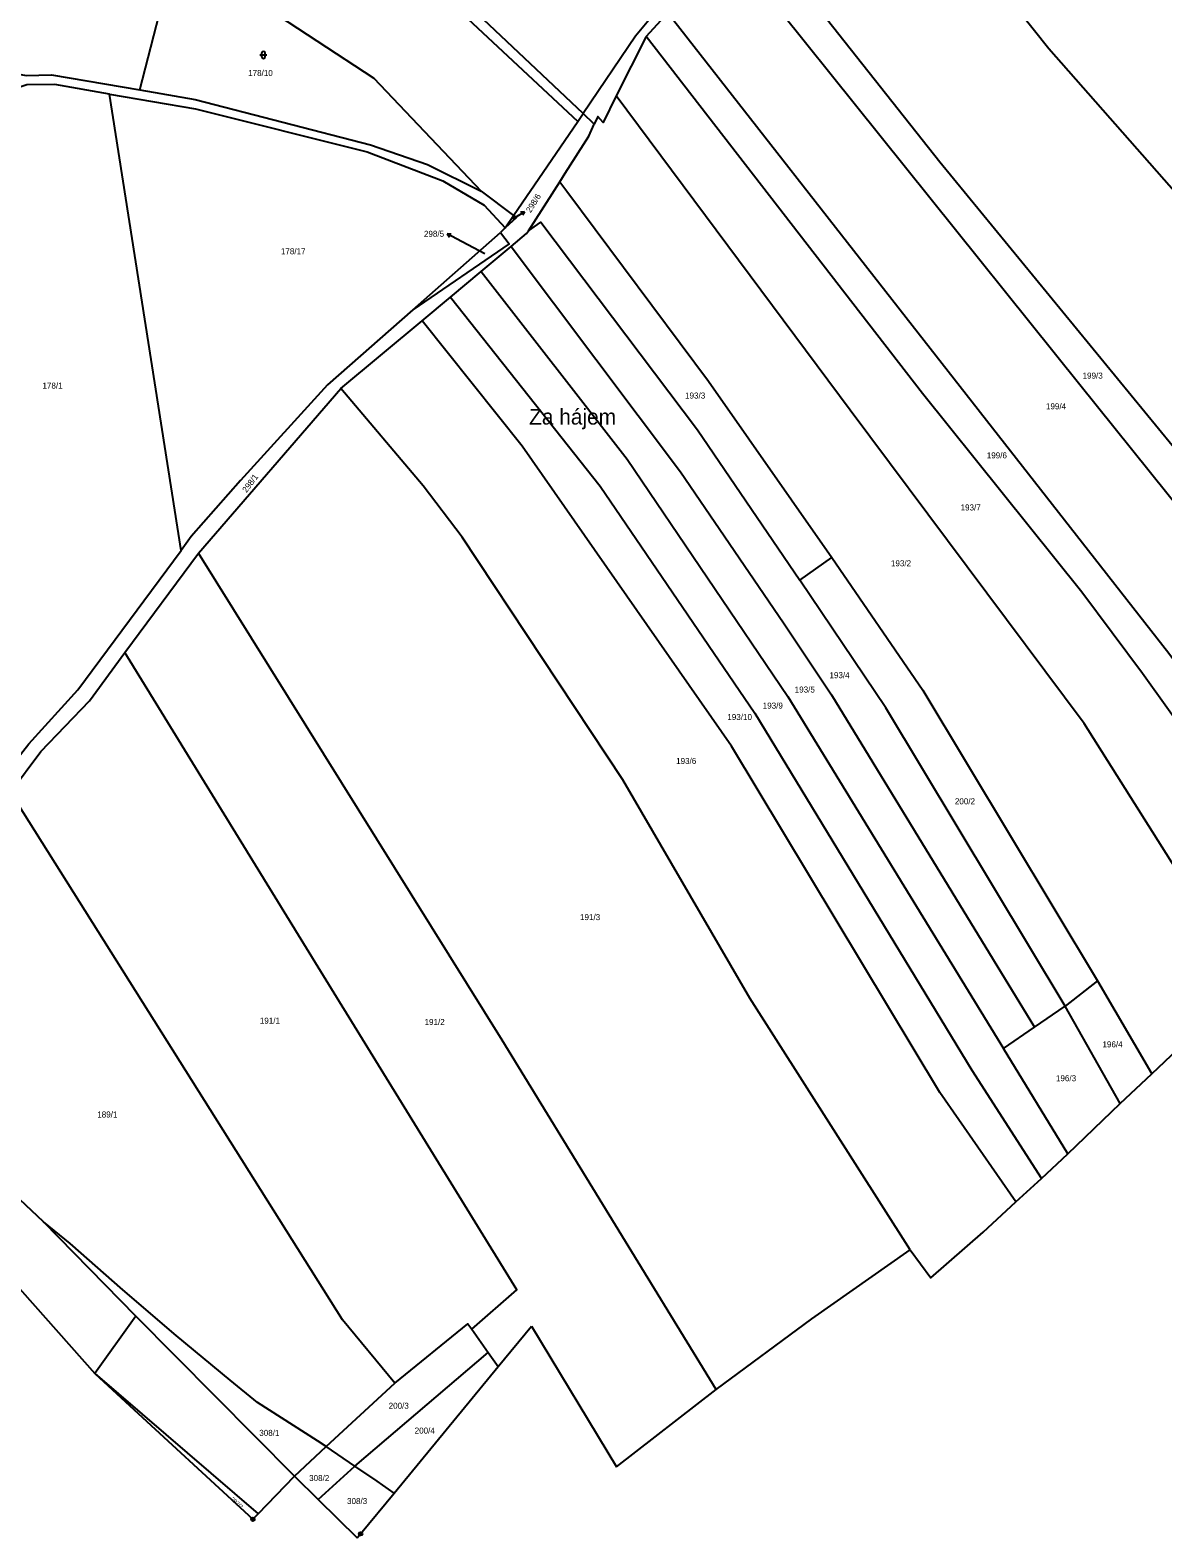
# Model space of a CAD drawing. Extents: x -779723 to -777378, y -1011169 to -1009297.
# Drawn here: x -779294.8 to -778975.2, y -1011169.3 to -1010743.9 of the extents above; entities that cross this region are included whole.
import ezdxf

# ---------------------------------------------------------------- set-up
doc = ezdxf.new("R2010")
doc.units = 0
for name, color, linetype in [('Hranice parcel', 7, 'Continuous'), ('Parcelní čísla', 7, 'Continuous'), ('Pop  PČ popisy', 7, 'Continuous'), ('Vnitřní kresba', 7, 'Continuous'), ('Značky bodu BP', 7, 'Continuous'), ('Značky kultur', 7, 'Continuous')]:
    doc.layers.add(name, color=color, linetype=linetype)

msp = doc.modelspace()

# ---------------------------------------------------------------- linework, layer by layer
at = {"layer": 'Hranice parcel'}
for p, q in [((-779114.85, -1010739.08), (-779121, -1010745.73)), ((-779121, -1010745.73), (-779129.44, -1010762.47)), ((-779252.21, -1010890.71), (-779272.43, -1010762.01)), ((-779140.28, -1010769.67), (-779138.78, -1010767.46)), ((-779135.61, -1010770.46), (-779138.78, -1010767.46)), ((-779154.19, -1010800.5), (-779145.37, -1010786.69)), ((-779167.5, -1010789.36), (-779158.36, -1010796.23)), ((-779160.74, -1010799.73), (-779162.08, -1010801.02)), ((-779160.74, -1010799.73), (-779158.36, -1010796.23)), ((-779186.85, -1010822.84), (-779162.08, -1010801.02)), ((-779167.52, -1010812.01), (-779159.1, -1010804.99)), ((-779176.17, -1010819.22), (-779167.52, -1010812.01)), ((-779184.17, -1010825.9), (-779176.17, -1010819.22)), ((-779207.15, -1010845.06), (-779184.17, -1010825.9)), ((-779247.3, -1010891.46), (-779207.15, -1010845.06)), ((-779268.1, -1010919.48), (-779247.3, -1010891.46)), ((-779077.58, -1010899.08), (-779068.64, -1010892.72)), ((-778993.64, -1011012.17), (-779002.79, -1011019.26)), ((-778993.64, -1011012.17), (-778978.29, -1011038.33)), ((-778978.29, -1011038.33), (-778951.63, -1011012.88)), ((-779011.43, -1011025.21), (-779002.79, -1011019.26)), ((-778987.21, -1011046.72), (-779002.79, -1011019.26)), ((-779020.18, -1011031.25), (-779011.43, -1011025.21)), ((-779002, -1011060.92), (-779020.18, -1011031.25)), ((-778987.21, -1011046.72), (-778978.29, -1011038.33)), ((-779291.02, -1011080.11), (-779333.53, -1011040.14)), ((-779002, -1011060.92), (-778987.21, -1011046.72)), ((-779009.48, -1011067.84), (-779002, -1011060.92)), ((-779016.68, -1011074.49), (-779009.48, -1011067.84)), ((-779320.15, -1011073.73), (-779276.53, -1011122.92)), ((-779170.13, -1011110.43), (-779165.54, -1011116.95)), ((-779162.74, -1011120.93), (-779153.37, -1011109.53)), ((-779153.37, -1011109.53), (-779129.33, -1011149.2)), ((-779203.15, -1011149.01), (-779165.54, -1011116.95)), ((-779165.54, -1011116.95), (-779162.74, -1011120.93)), ((-779276.53, -1011122.92), (-779230.46, -1011162.5)), ((-779276.53, -1011122.92), (-779269.1, -1011129.77)), ((-779192.08, -1011156.62), (-779162.74, -1011120.93)), ((-779211.28, -1011143.53), (-779191.88, -1011125.67)), ((-779129.33, -1011149.2), (-779101.21, -1011127.39)), ((-779269.1, -1011129.77), (-779231.93, -1011164.02)), ((-779220.18, -1011151.87), (-779211.28, -1011143.53)), ((-779203.15, -1011149.01), (-779211.28, -1011143.53)), ((-779213.5, -1011158.46), (-779203.15, -1011149.01)), ((-779230.46, -1011162.5), (-779220.18, -1011151.87)), ((-779220.18, -1011151.87), (-779213.5, -1011158.46)), ((-779201.55, -1011168.14), (-779192.08, -1011156.62)), ((-779213.5, -1011158.46), (-779202.55, -1011169.26)), ((-779231.93, -1011164.02), (-779230.46, -1011162.5)), ((-779202.55, -1011169.26), (-779201.55, -1011168.14))]:
    msp.add_line(p, q, dxfattribs=at)
for points in [[(-778962.2, -1010592.7), (-778981.13, -1010614.69), (-779002.08, -1010633.85), (-779026.1, -1010654.25), (-779058.33, -1010684.95), (-779095.53, -1010716.56), (-779116.46, -1010736.64), (-779124.03, -1010745.63), (-779138.78, -1010767.46)], [(-779090.15, -1010715.21), (-779038.14, -1010781.12), (-778964.83, -1010870.44), (-778892.41, -1010960.42)], [(-779034.27, -1010715.3), (-779007.39, -1010749.08), (-778971.37, -1010789.97), (-778959.93, -1010803), (-778909.95, -1010860.69)], [(-779096.96, -1010721.21), (-778998.61, -1010843.93), (-778900.11, -1010966.64)], [(-779263.87, -1010760.8), (-779255.21, -1010727.12), (-779251.52, -1010729.6), (-779246.07, -1010725.76)], [(-779246.07, -1010725.76), (-779197.77, -1010757.47), (-779167.5, -1010789.36)], [(-779140.28, -1010769.67), (-779174.03, -1010738.22), (-779183.15, -1010731.82)], [(-779138.78, -1010767.46), (-779171.89, -1010736.2), (-779180.57, -1010729.93)], [(-779114.85, -1010739.08), (-779044.24, -1010829.34), (-778973.49, -1010919.73), (-778924.2, -1010986.99)], [(-778932.03, -1010993.77), (-778944.73, -1010976.05), (-778980.97, -1010925.46), (-778998.02, -1010902.45), (-779043.05, -1010846.46), (-779121, -1010745.73)], [(-779301.43, -1010755.73), (-779295.87, -1010756.68), (-779288.73, -1010756.56), (-779263.87, -1010760.8)], [(-779272.43, -1010762.01), (-779287.82, -1010759.31), (-779295.7, -1010759.39), (-779302.08, -1010761.54), (-779305.1, -1010773.02), (-779315.22, -1010791.07), (-779322.47, -1010805.72), (-779322.23, -1010817.25), (-779316.65, -1010835.49), (-779326.21, -1010868.35), (-779330.24, -1010887.12), (-779328.45, -1010910.24), (-779323.27, -1010927.11), (-779316.18, -1010959.35), (-779318.65, -1010965.85), (-779320.4, -1010975.49), (-779319.32, -1010985.91)], [(-779272.43, -1010762.01), (-779248.15, -1010766.16), (-779199.71, -1010778.27), (-779178.37, -1010786.48), (-779166.68, -1010793.33), (-779160.74, -1010799.73)], [(-779263.87, -1010760.8), (-779248.18, -1010763.48), (-779198.78, -1010776.27), (-779182.71, -1010781.86), (-779167.5, -1010789.36)], [(-779129.44, -1010762.47), (-779133.14, -1010770), (-779134.58, -1010768.25), (-779135.61, -1010770.46)], [(-778951.63, -1011012.88), (-778964.98, -1010991), (-778997.44, -1010939.52), (-779063.39, -1010851.12), (-779129.44, -1010762.47)], [(-779158.36, -1010796.23), (-779148.79, -1010782.17), (-779140.28, -1010769.67)], [(-779145.37, -1010786.69), (-779143.83, -1010784.29), (-779137.14, -1010773.83), (-779135.61, -1010770.46)], [(-779145.37, -1010786.69), (-779143.35, -1010789.4), (-779103.43, -1010842.99), (-779068.64, -1010892.72)], [(-779158.36, -1010796.23), (-779157.56, -1010796.83), (-779160.74, -1010799.73)], [(-779154.19, -1010800.5), (-779150.71, -1010798.11), (-779106.53, -1010856.72), (-779077.58, -1010899.08)], [(-779162.08, -1010801.02), (-779159.66, -1010804.24), (-779186.85, -1010822.84)], [(-779159.1, -1010804.99), (-779154.73, -1010801.34), (-779154.19, -1010800.5)], [(-779159.1, -1010804.99), (-779111.3, -1010868.53), (-779082.24, -1010911.14), (-779068.7, -1010931.41), (-779011.43, -1011025.21)], [(-779167.52, -1010812.01), (-779126.3, -1010864.94), (-779081.05, -1010931.89), (-779020.18, -1011031.25)], [(-779176.17, -1010819.22), (-779133.97, -1010872.59), (-779090.28, -1010936.59), (-779029.06, -1011037.37), (-779009.48, -1011067.84)], [(-779186.85, -1010822.84), (-779210.91, -1010844.02), (-779235.44, -1010870.94), (-779249.3, -1010886.77), (-779252.21, -1010890.71)], [(-779016.68, -1011074.49), (-779038.09, -1011043.59), (-779096.86, -1010945.95), (-779155.93, -1010861.31), (-779184.17, -1010825.9)], [(-779046.54, -1011087.97), (-779091.73, -1011017), (-779127.56, -1010955.39), (-779172.91, -1010886.98), (-779183.86, -1010872.45), (-779207.15, -1010845.06)], [(-779319.32, -1010985.91), (-779302.98, -1010955.24), (-779295.1, -1010945.28), (-779281.31, -1010930.07), (-779252.21, -1010890.71)], [(-779101.21, -1011127.39), (-779161.56, -1011028.82), (-779247.3, -1010891.46)], [(-779068.64, -1010892.72), (-779042.92, -1010930.15), (-778993.64, -1011012.17)], [(-779002.79, -1011019.26), (-779053.4, -1010935.08), (-779077.58, -1010899.08)], [(-779300.33, -1010958.9), (-779291.76, -1010947.43), (-779278.06, -1010933.1), (-779268.1, -1010919.48)], [(-779170.13, -1011110.43), (-779157.5, -1011099.26), (-779212.73, -1011009.48), (-779268.1, -1010919.48)], [(-779191.88, -1011125.67), (-779206.63, -1011107.76), (-779300.33, -1010958.9)], [(-779046.54, -1011087.97), (-779040.69, -1011095.95), (-779025.91, -1011083.02), (-779016.68, -1011074.49)], [(-779211.28, -1011143.53), (-779213.67, -1011141.92), (-779230.65, -1011131.07), (-779238.35, -1011124.82), (-779253.59, -1011112.14), (-779268.67, -1011099.29), (-779283.53, -1011086.19), (-779291.02, -1011080.11)], [(-779220.18, -1011151.87), (-779264.99, -1011106.72), (-779291.02, -1011080.11)], [(-779101.21, -1011127.39), (-779074.2, -1011107.44), (-779046.54, -1011087.97)], [(-779191.88, -1011125.67), (-779171.25, -1011108.84), (-779170.13, -1011110.43)], [(-779192.08, -1011156.62), (-779196.84, -1011153.26), (-779203.15, -1011149.01)]]:
    msp.add_lwpolyline(points, dxfattribs=at)
at = {"layer": 'Pop  PČ popisy'}
for p, q in [((-779157.83, -1010796.73), (-779155.29, -1010795.14)), ((-779155.29, -1010795.14), (-779156.4, -1010795.25)), ((-779155.29, -1010795.14), (-779155.87, -1010796.09)), ((-779158.56, -1010797.19), (-779157.83, -1010796.73)), ((-779174.48, -1010802.81), (-779177.13, -1010801.4)), ((-779177.13, -1010801.4), (-779176.01, -1010801.43)), ((-779177.13, -1010801.4), (-779176.48, -1010802.31)), ((-779166.51, -1010807.07), (-779174.48, -1010802.81))]:
    msp.add_line(p, q, dxfattribs=at)
at = {"layer": 'Vnitřní kresba'}
msp.add_line((-779264.99, -1011106.72), (-779276.53, -1011122.92), dxfattribs=at)
at = {"layer": 'Značky bodu BP'}
for centre, radius in [((-779231.93, -1011164.02), 0.5), ((-779231.93, -1011164.02), 0.0303), ((-779201.55, -1011168.14), 0.5), ((-779201.55, -1011168.14), 0.0303)]:
    msp.add_circle(centre, radius, dxfattribs=at)
at = {"layer": 'Značky kultur'}
for p, q in [((-779229.96, -1010750.91), (-779227.96, -1010750.91)), ((-779229.46, -1010750.41), (-779229.46, -1010751.41)), ((-779228.46, -1010751.41), (-779228.46, -1010750.41))]:
    msp.add_line(p, q, dxfattribs=at)
for centre, start, end in [((-779228.96, -1010750.41), 0, 180), ((-779228.96, -1010751.41), 180, 359.9879)]:
    msp.add_arc(centre, 0.5, start, end, dxfattribs=at)

# ---------------------------------------------------------------- texts
at = {"layer": 'Parcelní čísla'}
for s, p in [('178/10', (-779233.27, -1010756.87)), ('298/5', (-779183.67, -1010802.24)), ('178/17', (-779224.03, -1010807.14)), ('199/3', (-778997.85, -1010842.24)), ('178/1', (-779291.3, -1010845.06)), ('193/3', (-779110, -1010847.86)), ('199/4', (-779008.18, -1010850.89)), ('199/6', (-779024.88, -1010864.74)), ('193/7', (-779032.27, -1010879.43)), ('193/2', (-779051.92, -1010895.18)), ('193/4', (-779069.26, -1010926.75)), ('193/5', (-779079.07, -1010930.8)), ('193/9', (-779088.09, -1010935.33)), ('193/10', (-779098.08, -1010938.55)), ('193/6', (-779112.53, -1010950.95)), ('200/2', (-779033.88, -1010962.32)), ('191/3', (-779139.64, -1010995)), ('191/1', (-779229.97, -1011024.21)), ('191/2', (-779183.5, -1011024.58)), ('196/4', (-778992.24, -1011030.89)), ('196/3', (-779005.36, -1011040.44)), ('189/1', (-779275.84, -1011050.68)), ('200/3', (-779193.63, -1011132.85)), ('308/1', (-779230.13, -1011140.5)), ('200/4', (-779186.29, -1011139.85)), ('308/2', (-779216.06, -1011153.24)), ('308/3', (-779205.37, -1011159.73))]:
    msp.add_text(s, height=1.7, dxfattribs=at).set_placement(p)
for s, height, rotation, p in [('298/6', 1.7, 58, (-779153.57, -1010795.58)), ('298/1', 1.7, 53, (-779233.74, -1010874.53)), ('297/2', 1.14, 318, (-779238.27, -1011158.51))]:
    msp.add_text(s, height=height, rotation=rotation, dxfattribs=at).set_placement(p)
at = {"layer": 'Pop  PČ popisy'}
msp.add_text('Za hájem', height=4.4, dxfattribs=at).set_placement((-779154, -1010855.2))

doc.saveas('drawing.dxf')
